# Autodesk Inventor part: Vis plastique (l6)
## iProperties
Author: Flavien MARTY
Shininess: 60.0
PropertySet Name: _Private Model Information
Created: 2001-10
Part Number: Vis plastique (l6)
Material: Par défaut
Document SubType Name: Modélisation
Designer: Flavien MARTY
Control State: 0
Master: False
Checked Out: False
PropertySet Name: Design Tracking Control
Density: 0.0
Volumn: 0.0
Area: 0.0
PropertySet Name: Model Information
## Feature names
1. Base1
